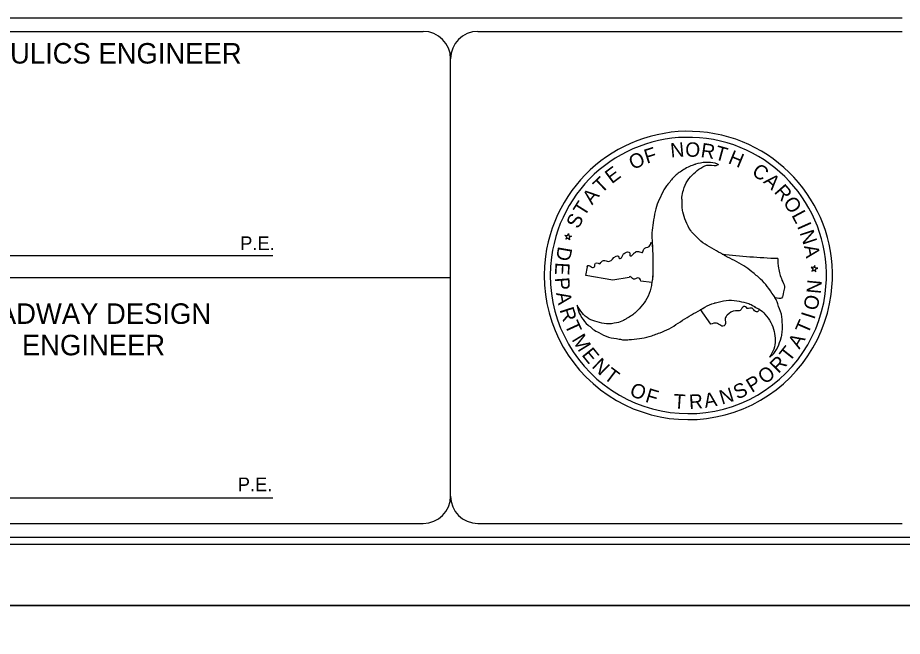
# Model space of a CAD drawing. Extents: x 2241278 to 2254132, y 649924 to 670434.
# Drawn here: x 2251201 to 2252819, y 660843 to 661974 of the extents above; entities that cross this region are included whole.
import ezdxf

# ---------------------------------------------------------------- set-up
doc = ezdxf.new("R2010")
doc.units = 0
for name, color, linetype in [('Sheet Cutting Line CELL', 7, 'Continuous'), ('Sheet Plot Border Inside CELL', 7, 'Continuous'), ('Sheet Plot Border Outside CELL', 7, 'Continuous'), ('Sheet Title CELL', 7, 'Continuous')]:
    doc.layers.add(name, color=color, linetype=linetype)

msp = doc.modelspace()

# ---------------------------------------------------------------- linework, layer by layer
at = {"layer": 'Sheet Cutting Line CELL'}
for p, q in [((2244558.8, 660899.2), (2252978.8, 660899.2)), ((2252978.8, 660899.2), (2244558.8, 660899.2))]:
    msp.add_line(p, q, dxfattribs=at)
at = {"layer": 'Sheet Plot Border Inside CELL'}
msp.add_lwpolyline([(2244623.8, 661011.4), (2252956.3, 661011.4), (2252956.3, 666286.9), (2244623.8, 666286.9)], close=True, dxfattribs=at)
at = {"layer": 'Sheet Plot Border Outside CELL'}
for points in [[(2252978.8, 666399.1), (2244558.8, 666399.1), (2244558.8, 660899.2), (2252978.8, 660899.2)], [(2244558.8, 655399.2), (2252978.8, 655399.2), (2252978.8, 660899.2), (2244558.8, 660899.2)]]:
    msp.add_lwpolyline(points, close=True, dxfattribs=at)
at = {"layer": 'Sheet Title CELL'}
for p, q in [((2245718.8, 661974.2), (2252818.8, 661974.2)), ((2250943.8, 661949.2), (2251942.6, 661949.2)), ((2252042.6, 661949.2), (2252818.8, 661949.2)), ((2251992.6, 661099.2), (2251992.6, 661899.2)), ((2252482.7, 661706.2), (2252482.1, 661705.7)), ((2252482.7, 661706.2), (2252482.1, 661705.7)), ((2252205, 661573.2), (2252201.8, 661576.4)), ((2252201.8, 661576.4), (2252206.3, 661575.8)), ((2252206.3, 661575.8), (2252208.1, 661579.8)), ((2252208.1, 661579.8), (2252209.1, 661575.4)), ((2252209.1, 661575.4), (2252213.6, 661574.8)), ((2252203.1, 661569), (2252205, 661573.2)), ((2252207, 661571.3), (2252203.1, 661569)), ((2252210.3, 661568), (2252207, 661571.3)), ((2252213.6, 661574.8), (2252209.5, 661572.6)), ((2252209.5, 661572.6), (2252210.3, 661568)), ((2250946.2, 661539.2), (2251667.5, 661539.2)), ((2252489.3, 661542), (2252489.3, 661542)), ((2252240, 661502.8), (2252242.7, 661518.4)), ((2252656.6, 661517.3), (2252652.1, 661517.9)), ((2252652.1, 661517.9), (2252655.5, 661514.8)), ((2252655.5, 661514.8), (2252653.6, 661510.6)), ((2252653.6, 661510.6), (2252657.4, 661512.8)), ((2252658.6, 661521.3), (2252656.6, 661517.3)), ((2252657.4, 661512.8), (2252660.7, 661509.7)), ((2252659.6, 661516.9), (2252658.6, 661521.3)), ((2252664, 661516.5), (2252659.6, 661516.9)), ((2252660, 661514.2), (2252664, 661516.5)), ((2252660.7, 661509.7), (2252660, 661514.2)), ((2250889.3, 661499.3), (2251992.6, 661499.3)), ((2252289.4, 661494.3), (2252240, 661502.8)), ((2252318.9, 661498.9), (2252289.4, 661494.3)), ((2252360.9, 661489.8), (2252340.3, 661492.7)), ((2252688.7, 661468.1), (2252688.7, 661468.1)), ((2252468.4, 661413.8), (2252449.7, 661440.4)), ((2252449.7, 661440.4), (2252449.7, 661440.4)), ((2250960, 661096.4), (2251667.5, 661096.4))]:
    msp.add_line(p, q, dxfattribs=at)
for points in [[(2250943.8, 661049.2), (2251942.6, 661049.2)], [(2252042.6, 661049.2), (2252818.8, 661049.2)], [(2245443.8, 661024.1), (2252843.8, 661024.1)]]:
    msp.add_lwpolyline(points, dxfattribs=at)
for centre, radius, start, end in [((2251942.6, 661899.2), 50, 0, 90), ((2252042.6, 661899.2), 50, 90, 180), ((2252427.4, 661502.9), 263.6, 352.4211, 172.4211), ((2252427.4, 661502.9), 252.6, 352.4211, 172.4211), ((2252645.6, 662922.9), 1389.7, 258.0996, 258.1992), ((2252427.4, 661502.9), 263.6, 172.4211, 352.4211), ((2252427.4, 661502.9), 252.6, 172.4211, 352.4211), ((2252645.6, 662922.9), 1389.7, 263.5387, 267.7447), ((2251942.6, 661099.5), 50, 270, 360), ((2252042.6, 661099.5), 50, 180, 270)]:
    msp.add_arc(centre, radius, start, end, dxfattribs=at)
for points in [[(2252482.1, 661705.7), (2252476.4, 661708), (2252459, 661709.6), (2252440.6, 661706.3), (2252438.9, 661705.7), (2252429.5, 661702.2), (2252419.2, 661696.5), (2252403.2, 661685), (2252390.2, 661669.9), (2252384.9, 661663.4), (2252380.6, 661655.2), (2252372.3, 661637.5), (2252366.9, 661620.1), (2252363, 661599.4), (2252360.9, 661581.1), (2252361.4, 661562.1), (2252362.2, 661542.8), (2252362.4, 661524.2), (2252362.5, 661505), (2252360.1, 661486.3), (2252359.8, 661484.7), (2252353.8, 661465.3), (2252343.4, 661448.9), (2252331.1, 661435.6), (2252324.1, 661429.7), (2252314.4, 661424.1), (2252309, 661420.8), (2252296.3, 661416.3), (2252277.9, 661414.5), (2252260.5, 661417.9), (2252245.5, 661423.9), (2252233.1, 661434.4), (2252224, 661448.4)], [(2252576, 661353.6), (2252580.6, 661357.2), (2252590.9, 661371.5), (2252597.2, 661389.1), (2252597.7, 661390.9), (2252599.2, 661400.8), (2252599.4, 661412.7), (2252597.6, 661432.3), (2252590.9, 661451), (2252588.1, 661458.8), (2252583, 661466.8), (2252571.9, 661482.7), (2252559.5, 661496.1), (2252543.5, 661509.8), (2252528.7, 661520.6), (2252511.9, 661530), (2252494.9, 661538.9), (2252478.8, 661547.9), (2252461.9, 661557.5), (2252447, 661568.9), (2252445.9, 661570), (2252431.8, 661585), (2252422.9, 661602.2), (2252417.4, 661619.4), (2252416.1, 661628.3), (2252416, 661639.6), (2252415.7, 661646.1), (2252418.4, 661659.1), (2252426, 661676.2), (2252437.5, 661689.4), (2252450.2, 661699.3), (2252465.7, 661704.8), (2252482.1, 661705.7), (2252482.7, 661706.2)], [(2252242.7, 661518.4), (2252242.3, 661520), (2252245.2, 661521.3), (2252252.1, 661517.3), (2252256.3, 661520), (2252256.5, 661523.2), (2252259.9, 661526), (2252264.8, 661524.3), (2252270.2, 661529.5), (2252274.5, 661530), (2252283.3, 661528.8), (2252295.2, 661537.9), (2252299.7, 661538), (2252300.4, 661535), (2252303, 661534.1), (2252308.7, 661542.2), (2252310, 661543.3), (2252318.6, 661545.4), (2252320.6, 661543.6), (2252320.7, 661539.7), (2252321.7, 661538.7), (2252324.7, 661540.3), (2252329, 661544.5), (2252336.2, 661547), (2252343.7, 661545.1), (2252345.9, 661551.2), (2252355.7, 661556), (2252358, 661559.4), (2252359, 661563.1)], [(2252361.4, 661562.5), (2252361.4, 661562.1), (2252362.2, 661542.8), (2252362.4, 661524.2), (2252362.5, 661505), (2252360.9, 661489.8)], [(2252586.5, 661461.9), (2252583, 661466.8), (2252571.9, 661482.7), (2252559.5, 661496.1), (2252543.5, 661509.8), (2252528.7, 661520.6), (2252511.9, 661530), (2252494.9, 661538.9), (2252489.3, 661542)], [(2252590.9, 661534.2), (2252592.3, 661516.3), (2252598.7, 661494.5), (2252603.1, 661482.5), (2252601.7, 661472.9), (2252597.9, 661461.6), (2252586.6, 661462)], [(2252340.3, 661492.7), (2252338.8, 661496.8), (2252334.9, 661498.5), (2252329.1, 661496.4), (2252325, 661497.1), (2252321, 661501), (2252318.9, 661498.9)], [(2252224, 661448.4), (2252225.1, 661442.3), (2252232.3, 661426.3), (2252244.3, 661412), (2252245.6, 661411), (2252253.5, 661404.4), (2252263.6, 661398.4), (2252281.6, 661390.2), (2252301, 661386.7), (2252309.2, 661385.2), (2252319, 661385.6), (2252337.9, 661387.4), (2252355.6, 661391.2), (2252375.6, 661398.3), (2252392.4, 661405.6), (2252408.8, 661415.6), (2252425, 661426), (2252441.1, 661435.4), (2252457.8, 661445), (2252475.1, 661452.4), (2252476.9, 661452.8), (2252496.8, 661457.4), (2252515.9, 661456.6), (2252533.3, 661452.7), (2252542.3, 661449.6), (2252551.7, 661443.8), (2252557.7, 661440.9), (2252567.6, 661432.1), (2252578.3, 661417), (2252584.2, 661400.5), (2252586.4, 661384.3), (2252583.5, 661368.3), (2252576, 661353.6)], [(2252449.7, 661440.4), (2252457.8, 661445), (2252475.1, 661452.4), (2252476.9, 661452.8), (2252496.8, 661457.4), (2252515.9, 661456.6), (2252533.3, 661452.7), (2252542.3, 661449.6), (2252551.7, 661443.8), (2252557.2, 661441)], [(2252557.2, 661441), (2252554.1, 661436.7), (2252550.2, 661436.9), (2252544, 661443.3), (2252535.3, 661442.8), (2252531.8, 661445.5), (2252529.2, 661445.9), (2252522.1, 661439.1), (2252513.5, 661438.3), (2252498.6, 661430.2), (2252495, 661424.7), (2252494.4, 661412), (2252490.7, 661410), (2252486.8, 661411.2), (2252478.8, 661415.5), (2252468.4, 661413.8)]]:
    msp.add_spline(points, degree=3, dxfattribs=at)

# ---------------------------------------------------------------- texts
for s, height, rotation, p in [(' HYDRAULICS ENGINEER', 37.5, 360, (2250997.3, 661890.4)), ('F', 26.3, 17.4918, (2252351.4, 661706.9)), ('N', 26.3, 5.4049, (2252395.7, 661718.3)), ('O', 26.3, 357.9068, (2252421.3, 661720.5)), ('R', 26.3, 351.2969, (2252449, 661719.5)), ('T', 26.3, 344.6472, (2252473.9, 661715.7)), ('O', 26.3, 24.6387, (2252326, 661695.5)), ('H', 26.2, 337.5625, (2252498.7, 661708.7)), ('C', 26.2, 325.2202, (2252541.7, 661688.4)), ('E', 26.2, 36.5781, (2252287.3, 661669.6)), ('T', 26.2, 43.6937, (2252268.6, 661651.9)), ('A', 26.3, 317.7231, (2252563.2, 661673.3)), ('A', 26.4, 50.7489, (2252251.4, 661630.8)), ('R', 26.3, 311.3592, (2252583.1, 661655.2)), ('T', 26.3, 57.8012, (2252237.4, 661609.3)), ('O', 26.3, 304.2396, (2252599.7, 661636.3)), ('S', 26.3, 64.1774, (2252226.5, 661586.8)), ('L', 26.2, 298.0059, (2252615.5, 661613.1)), ('I', 26.3, 294.0166, (2252625.7, 661592.9)), ('N', 26.3, 288.3165, (2252630.7, 661581.1)), ('P.E.', 25, 360, (2251607.7, 661549.4)), ('D', 26.3, 260.2741, (2252189.4, 661557)), ('A', 26.3, 280.8845, (2252638.7, 661556.5)), ('E', 26.2, 266.562, (2252184.6, 661527.3)), ('P', 26.3, 274.0944, (2252183.4, 661498.7)), ('N', 26.3, 84.6293, (2252669.4, 661468.5)), ('A', 26.2, 280.687, (2252185.4, 661470.7)), ('O', 26.2, 77.3812, (2252662.8, 661437.5)), ('ROADWAY DESIGN', 37.497, 360, (2251089.3, 661414.4)), ('R', 26.3, 287.7556, (2252191.5, 661440.2)), ('I', 26.3, 72.2456, (2252657.8, 661421.3)), ('T', 26.3, 294.4062, (2252200.6, 661412.7)), ('T', 26.2, 66.5957, (2252646.1, 661394.1)), ('ENGINEER', 37.5, 360, (2251208.5, 661356.9)), ('M', 26.2, 301.6412, (2252213.3, 661385.7)), ('A', 26.3, 59.5113, (2252630.6, 661367)), ('E', 26.2, 309.108, (2252231.3, 661357.5)), ('T', 26.2, 51.4242, (2252612.4, 661343.4)), ('N', 26.3, 316.0795, (2252249.5, 661335.7)), ('R', 26.3, 45.3245, (2252592.2, 661322.5)), ('T', 26.2, 322.9215, (2252271.1, 661315.3)), ('O', 26.3, 38.1354, (2252567.4, 661302.7)), ('P', 26.3, 31.4434, (2252543.5, 661287.8)), ('O', 26.3, 336.2252, (2252318, 661284.6)), ('S', 26.2, 24.2515, (2252517, 661275.7)), ('F', 26.3, 343.3904, (2252347.2, 661272.2)), ('T', 26.2, 356.2997, (2252399.6, 661260.2)), ('R', 26.3, 3.2563, (2252429.3, 661258.6)), ('A', 26.2, 10.0094, (2252458.3, 661260.6)), ('N', 26.2, 17.041, (2252488.8, 661266.5)), ('P.E.', 25, 360, (2251603.3, 661108.4))]:
    msp.add_text(s, height=height, rotation=rotation, dxfattribs=at).set_placement(p)

doc.saveas('drawing.dxf')
